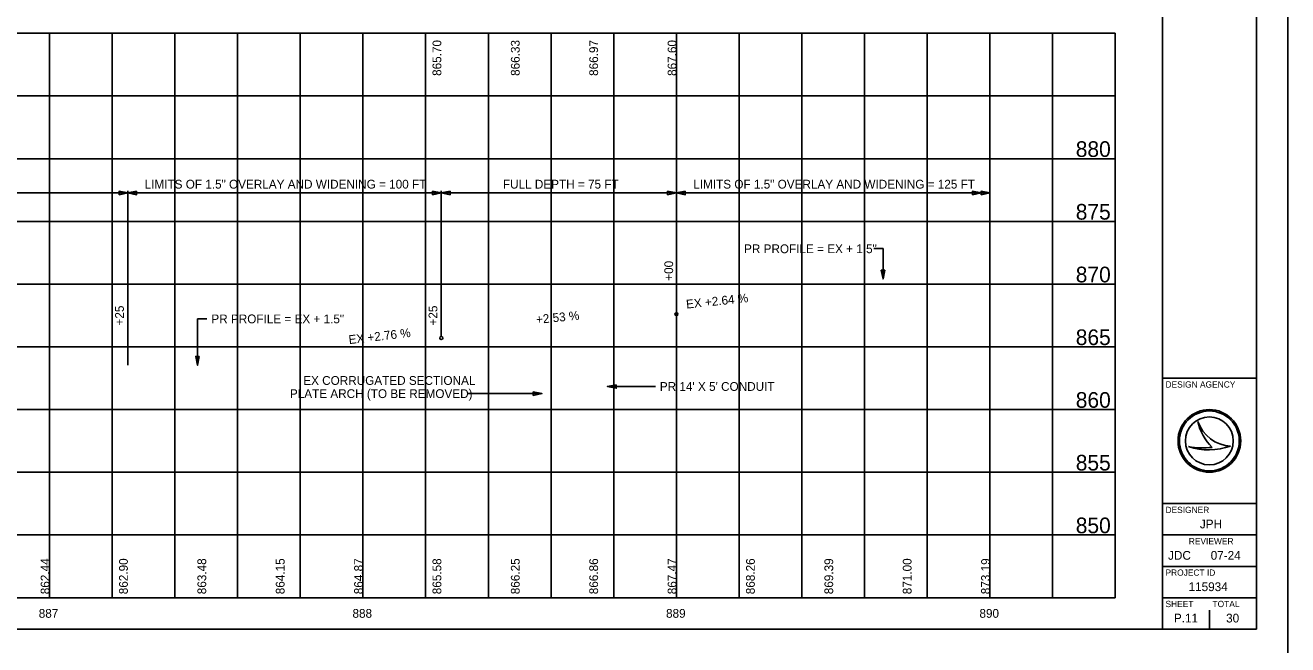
# Model space of a CAD drawing. Extents: x 0 to 2520, y -440 to 502.
# Drawn here: x 277.3 to 680, y 5 to 202.5 of the extents above; entities that cross this region are included whole.
import ezdxf

# ---------------------------------------------------------------- set-up
doc = ezdxf.new("R2010")
doc.units = 0
for name, color, linetype in [('DR_X_Culvert', 7, 'Continuous'), ('MT_P_Edge_Line', 7, 'Continuous'), ('PF_P_Grade_Line', 7, 'Continuous'), ('PF_X_Ground_Line', 7, 'Continuous'), ('TX_P_1', 7, 'Continuous'), ('XS_P_Finished_Grade', 7, 'Continuous'), ('XS_X_Pavt', 7, 'Continuous')]:
    doc.layers.add(name, color=color, linetype=linetype)

msp = doc.modelspace()

# ---------------------------------------------------------------- linework, layer by layer
at = {"layer": 'DR_X_Culvert'}
msp.add_lwpolyline([(0, 0), (680, 0), (680, 440), (0, 440)], close=True, dxfattribs=at)
at = {"layer": 'MT_P_Edge_Line'}
msp.add_line((418.58, 85.07), (442.11, 85.07), dxfattribs=at)
at = {"layer": 'PF_P_Grade_Line'}
for p, q in [((310, 149.07), (159, 149.07)), ((310, 94.13), (310, 149.7)), ((410, 149.07), (310, 149.07)), ((410, 103.3), (410, 149.7)), ((410, 149.07), (485, 149.07)), ((485, 110.89), (485, 149.7)), ((485, 149.07), (585, 149.07)), ((550.89, 131.32), (547.96, 131.32)), ((550.89, 121.64), (550.89, 131.32)), ((332.24, 94.15), (332.24, 108.96)), ((335.16, 108.96), (332.24, 108.96)), ((478.34, 87.36), (463, 87.36))]:
    msp.add_line(p, q, dxfattribs=at)
for centre in [(485, 110.4), (410, 102.81)]:
    msp.add_circle(centre, 0.49, dxfattribs=at)
at = {"layer": 'PF_X_Ground_Line'}
for p, q in [((45, 200), (625, 200)), ((625, 20), (625, 200)), ((651.35, 76.19), (651.35, 76.19)), ((655, 70), (655, 70)), ((648.34, 68.19), (648.34, 68.19)), ((661.75, 68.37), (661.75, 68.37)), ((45, 20), (625, 20)), ((647.5, 13.5), (647.5, 13.5)), ((655, 10), (655, 16))]:
    msp.add_line(p, q, dxfattribs=at)
for radius in [10, 9.54, 9.54, 7.64]:
    msp.add_circle((655, 70), radius, dxfattribs=at)
for centre, radius, start, end in [((662.32, 79.95), 11.6, 198.9257, 198.9319), ((666.93, 79.4), 15.91, 191.6379, 191.6421), ((662.32, 79.95), 11.6, 198.9319, 267.1657), ((666.93, 79.4), 15.91, 191.6421, 226.0947), ((654.79, 87.4), 20.26, 251.4576, 290.0832), ((652.96, 93.09), 25.32, 259.4964, 259.4995), ((654.79, 87.4), 20.26, 251.4527, 251.4576), ((652.96, 93.09), 25.32, 259.4995, 276.6672)]:
    msp.add_arc(centre, radius, start, end, dxfattribs=at)
at = {"layer": 'TX_P_1'}
for p, q in [((640, 10), (640, 430)), ((640, 90), (670, 90)), ((640, 50), (670, 50)), ((640, 40), (670, 40)), ((640, 30), (670, 30)), ((640, 20), (670, 20))]:
    msp.add_line(p, q, dxfattribs=at)
msp.add_lwpolyline([(30, 430), (670, 430), (670, 10), (30, 10)], close=True, dxfattribs=at)
at = {"layer": 'XS_P_Finished_Grade'}
for points in [[(307.2, 148.51), (307.2, 149.63), (310, 149.07)], [(312.8, 149.63), (312.8, 148.51), (310, 149.07)], [(407.2, 148.51), (407.2, 149.63), (410, 149.07)], [(412.8, 149.63), (412.8, 148.51), (410, 149.07)], [(482.2, 148.51), (482.2, 149.63), (485, 149.07)], [(487.8, 149.63), (487.8, 148.51), (485, 149.07)], [(579.4, 148.51), (579.4, 149.63), (582.2, 149.07)], [(582.2, 148.51), (582.2, 149.63), (585, 149.07)], [(551.45, 124.44), (550.33, 124.44), (550.89, 121.64)], [(332.8, 96.95), (331.68, 96.95), (332.24, 94.15)], [(439.31, 84.51), (439.31, 85.63), (442.11, 85.07)], [(465.8, 87.92), (465.8, 86.8), (463, 87.36)]]:
    msp.add_lwpolyline(points, close=True, dxfattribs=at)
at = {"layer": 'XS_X_Pavt'}
for p, q in [((285, 20), (285, 200)), ((305, 20), (305, 200)), ((325, 20), (325, 200)), ((345, 20), (345, 200)), ((365, 20), (365, 200)), ((385, 20), (385, 200)), ((405, 20), (405, 200)), ((425, 20), (425, 200)), ((445, 20), (445, 200)), ((465, 20), (465, 200)), ((485, 20), (485, 200)), ((505, 20), (505, 200)), ((525, 20), (525, 200)), ((545, 20), (545, 200)), ((565, 20), (565, 200)), ((585, 20), (585, 200)), ((605, 20), (605, 200)), ((45, 180), (625, 180)), ((45, 160), (625, 160)), ((45, 140), (625, 140)), ((45, 120), (625, 120)), ((45, 100), (625, 100)), ((45, 80), (625, 80)), ((45, 60), (625, 60)), ((45, 40), (625, 40))]:
    msp.add_line(p, q, dxfattribs=at)

# ---------------------------------------------------------------- texts
at = {"layer": 'MT_P_Edge_Line'}
for s, rotation, p in [('865.70', 90, (410, 186.39)), ('866.33', 90, (435, 186.39)), ('866.97', 90, (460, 186.39)), ('867.60', 90, (485, 186.39)), ('+00', 90, (483.94, 121.07)), ('EX +2.64 %', 5.9893, (488.23, 112.18)), ('+25', 90, (308.74, 106.81)), ('+25', 90, (408.74, 106.81)), ('EX +2.76 %', 6.7014, (380.6, 100.86)), ('862.44', 90, (285, 21.1)), ('862.90', 90, (310, 21.1)), ('863.48', 90, (335, 21.1)), ('864.15', 90, (360, 21.1)), ('864.87', 90, (385, 21.1)), ('865.58', 90, (410, 21.1)), ('866.25', 90, (435, 21.1)), ('866.86', 90, (460, 21.1)), ('867.47', 90, (485, 21.1)), ('868.26', 90, (510, 21.1)), ('869.39', 90, (535, 21.1)), ('871.00', 90, (560, 21.1)), ('873.19', 90, (585, 21.1))]:
    msp.add_text(s, height=2.8, rotation=rotation, dxfattribs=at).set_placement(p)
for s, p in [('EX CORRUGATED SECTIONAL', (365.95, 87.87)), ('PLATE ARCH (TO BE REMOVED)', (361.7, 83.67)), ('887', (281.58, 13.6)), ('888', (381.66, 13.6)), ('889', (481.68, 13.6)), ('890', (581.65, 13.6))]:
    msp.add_text(s, height=2.8, dxfattribs=at).set_placement(p)
at = {"layer": 'PF_P_Grade_Line'}
for s, p in [('LIMITS OF 1.5" OVERLAY AND WIDENING = 100 FT', (315.36, 150.47)), ('FULL DEPTH = 75 FT', (429.64, 150.47)), ('LIMITS OF 1.5" OVERLAY AND WIDENING = 125 FT', (490.36, 150.47)), ('PR PROFILE = EX + 1.5"', (506.57, 129.87)), ('PR PROFILE = EX + 1.5"', (336.65, 107.51)), ("PR 14' X 5' CONDUIT", (479.7, 85.96))]:
    msp.add_text(s, height=2.8, dxfattribs=at).set_placement(p)
msp.add_text('+2.53 %', height=2.8, rotation=5.7756, dxfattribs=at).set_placement((440.35, 107.29))
at = {"layer": 'PF_X_Ground_Line'}
for s, height, p in [('880', 5, (612.38, 160.56)), ('875', 5, (612.38, 140.56)), ('870', 5, (612.38, 120.56)), ('865', 5, (612.38, 100.56)), ('DESIGN AGENCY', 2, (641, 87)), ('860', 5, (612.38, 80.56)), ('855', 5, (612.38, 60.56)), ('DESIGNER', 2, (641, 47)), ('850', 5, (612.38, 40.56)), ('JPH', 2.8, (651.97, 42.1)), ('REVIEWER', 2, (648.44, 37)), ('JDC', 2.8, (641.82, 32.1)), ('07-24', 2.8, (655.42, 32.1)), ('PROJECT ID', 2, (641, 27)), ('115934', 2.8, (648.36, 22.1)), ('SHEET', 2, (641, 17)), ('TOTAL', 2, (656, 17)), ('P.11', 2.8, (643.69, 12.1)), ('30', 2.8, (660.34, 12.1))]:
    msp.add_text(s, height=height, dxfattribs=at).set_placement(p)

doc.saveas('drawing.dxf')
